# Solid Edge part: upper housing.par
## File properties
Author: Robert a Rhodes jr
Template: NORMENG.PAR
Last saved by: Cadcim
Revision: 10
Application: Solid Edge
Accuracy: 0.99
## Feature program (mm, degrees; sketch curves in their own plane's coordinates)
sketch for "unnamed Protrusion 1" plane through (0, 0, 0) normal (0, -1, 0) x-axis (1, 0, 0)
  arc centre (0, 0) radius 152.4 from (152.4, 0) to (-152.4, 0) ccw
  line (-152.4, 0) -> (152.4, 0)
extrude "unnamed Protrusion 1" add finite 203.2 symmetric
swept protrusion "SweptProtrusion_1"  Profile_5_Plane_FractionOfCurve = 0
fillet "Round_1" radius 38.1
fillet "Round_2" radius 12.7
thinwall "Thinwall_2"  Thickness = 6.35 mm
sketch for "unnamed Cutout 1" plane through (0, -101.6, 76.2) normal (0, -1, 0) x-axis (1, 0, 0)
  arc centre (0, -76.2) radius 123.825 from (-123.825, -76.2) to (123.825, -76.2) cw
extrude "unnamed Cutout 1" cut through along -normal
sketch for "unnamed Cutout 2" plane through (0, 95.25, 73.025) normal (0, -1, 0) x-axis (1, 0, 0)
  arc centre (0, -73.025) radius 38.1 from (38.1, -73.025) to (-38.1, -73.025) ccw
extrude "unnamed Cutout 2" cut through along -normal
sketch for "ExtrudedProtrusion_2" plane through (0, -101.6, 76.2) normal (0, -1, 0) x-axis (1, 0, 0)
  line (152.4, -76.2) -> (190.5, -76.2)
  line (190.5, -76.2) -> (190.5, -66.04)
  line (190.5, -66.04) -> (152.061, -66.04)
  arc centre (0, -76.2) radius 152.4 from (152.4, -76.2) to (152.061, -66.04) ccw
extrude "ExtrudedProtrusion_2" add finite 203.2 along -normal
mirror "unnamed Mirror 1" of "ExtrudedProtrusion_2" about plane through (0, 0, 0) normal (1, 0, 0)
extrude "unnamed Protrusion 2" add finite 203.2
sketch for "Hole_1" plane through (171.2507, 0, 10.16) normal (0, 0, 1) x-axis (0, 1, 0)
hole "Hole_1" diameter 10.414 through
pattern "unnamed Pattern 1" of "Hole_1"
pattern "unnamed Pattern 2"
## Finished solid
Body 1: solid body, 69 faces, 164 edges, 88 vertices.
  Faces by surface: blend 24, plane 15, cylinder 14, offset 6, spline 6, torus 4
  Edges by curve: circle 60, intersection 56, line 45, curve on surface 3
Bounding box of the edges (mm; curved faces can reach further): 492.760 x 203.200 x 255.273, from (-302.26, -101.6, 0) to (190.5, 101.6, 255.2731).
Cylindrical faces by radius (mm): R5.207 x8, R12.7 x1, R19.05 x1, R38.1 x1, R123.825 x1, R146.05 x1, R152.4 x1
Toroidal faces (ring radius, tube radius in mm): R165.1 r12.7 x2, R165.1 r19.05 x2
Planar faces by outward normal: +x 1, +y 4, +z 2, -x 2, -y 4, -z 2
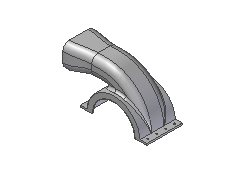
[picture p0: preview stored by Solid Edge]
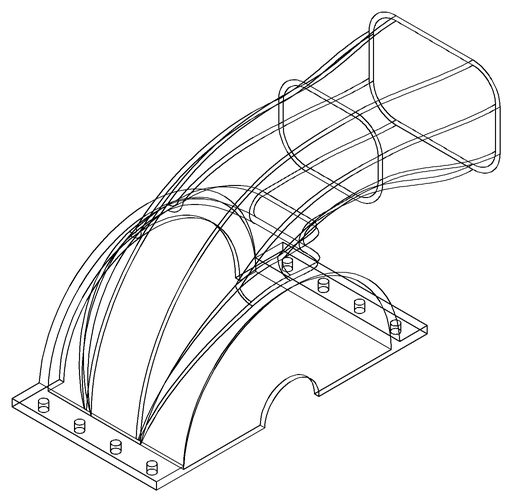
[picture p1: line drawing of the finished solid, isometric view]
